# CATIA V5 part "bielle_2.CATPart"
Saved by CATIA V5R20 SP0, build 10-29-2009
Part number: bielle1
Bounding box of the stored display mesh (mm): x 0 to 110, y -350 to 0, z -50 to 0
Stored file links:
  C:\Users\Noëllie\Documents\IFMA\2A\S3\IAO\Projet Artobolevski\Catia\bielle_2.CATPart
  C:\Users\Noëllie\Documents\IFMA\2A\S3\IAO\Projet Artobolevski\Catia\Artobolevski 782.CATProduct
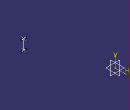
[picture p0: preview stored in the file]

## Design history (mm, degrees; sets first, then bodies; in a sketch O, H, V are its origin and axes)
Set1
  Point1 "B1g": linked copy from another document
  Point2 "C1": linked copy from another document
Body1 (main body)
  Line1 "bielle_barre": type PtPt, FirstPoint Point1, SecondPoint Point2
  Line2 "bielle_pivotsup": type PtDir, RefPoint Point1, Direction yz-plane, Start 10, End -10
  Line3 "bielle_pivotinf": type PtDir, RefPoint Point2, Direction yz-plane, Start 10, End -10
  Sketch1 on yz-plane, origin (0, 0, 0), H (0, 1, 0), V (0, 0, 1)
